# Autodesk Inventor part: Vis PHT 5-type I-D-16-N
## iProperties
Created: 2011-01
Part Number: Vis PHT 5-type I-D-16-N
Document SubType Name: Modeling
Designer: eric
Density: 1 g/cm^3
Mass: 0.495839 g
Surface Area: 5.16278 cm^2
Volume: 0.495839 cm^3
Author: eric
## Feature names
1. Base1
